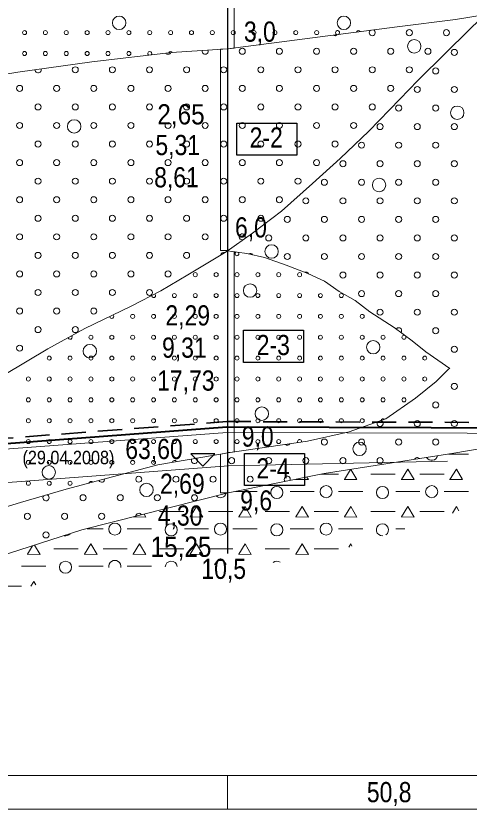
# Model space of a CAD drawing. Extents: x 640121 to 640955, y 6441885 to 6442246.
# Drawn here: x 640296.5 to 640363.9, y 6442063 to 6442180.9 of the extents above; entities that cross this region are included whole.
import ezdxf
from ezdxf.enums import TextEntityAlignment as Align

# ---------------------------------------------------------------- set-up
doc = ezdxf.new("R2010")
doc.units = 0
doc.header["$LTSCALE"] = 1.2
doc.linetypes.add('MEDIUM_DASHED', pattern=[4.5, 3, -1.5])
for name, color, linetype, lineweight in [('30', 7, 'Continuous', 13), ('31', 7, 'Continuous', 13), ('32', 7, 'Continuous', 13), ('33', 7, 'Continuous', 13), ('34', 7, 'Continuous', 25), ('35', 7, 'Continuous', 35), ('42', 7, 'Continuous', 13), ('43', 7, 'Continuous', 13), ('46', 7, 'Continuous', 13), ('47', 7, 'Continuous', 13)]:
    doc.layers.add(name, color=color, linetype=linetype, lineweight=lineweight)

msp = doc.modelspace()

# ---------------------------------------------------------------- linework, layer by layer
at = {"layer": '30'}
for p, q in [((640132.09, 6442068), (640510.5, 6442068)), ((640327.97, 6442068), (640327.97, 6442063)), ((640132.09, 6442063), (640510.5, 6442063))]:
    msp.add_line(p, q, dxfattribs=at)
at = {"layer": '31'}
for points in [[(640247.7, 6442147.03), (640257.72, 6442155.14), (640263.61, 6442159.68), (640268.14, 6442162.86), (640273.1, 6442165.63), (640278.29, 6442168.02), (640283.66, 6442169.95), (640287.74, 6442171.02), (640296.83, 6442172.52), (640307.85, 6442174.05), (640319.67, 6442175.43), (640328.02, 6442175.98), (640353.21, 6442179.27), (640361.87, 6442180.35), (640370.38, 6442181.71)], [(640227.02, 6442092.74), (640246.99, 6442098.72), (640259.67, 6442104.25), (640268.82, 6442109.45), (640277.74, 6442115.86), (640286.04, 6442121.74), (640294.93, 6442127.57), (640301.29, 6442131.41), (640306.79, 6442134.4), (640313.67, 6442137.73), (640318.09, 6442140.03), (640322.12, 6442142.41), (640327.78, 6442145.84), (640331.69, 6442148.58), (640336.02, 6442151.86), (640340.61, 6442155.98), (640344.72, 6442159.66), (640348.97, 6442163.76), (640353.58, 6442168.51), (640356.29, 6442171.26), (640360.44, 6442175.41), (640363.8, 6442178.7), (640365.59, 6442180.42)], [(640156.71, 6442084.57), (640169.39, 6442084.94), (640174.39, 6442085), (640185.27, 6442085.01), (640198.57, 6442085.15), (640211.29, 6442085.53), (640222.23, 6442086.04), (640236.05, 6442086.58), (640247.59, 6442087.26), (640261.87, 6442089), (640272.13, 6442093.03), (640281.27, 6442096.49), (640290.79, 6442099.48), (640306.37, 6442104.48), (640328.11, 6442110.01), (640342.33, 6442112.86), (640361.6, 6442115.89), (640378.77, 6442118.83), (640434.25, 6442118.61), (640476.5, 6442139.76), (640496.42, 6442148.93), (640502.36, 6442149.59), (640510.5, 6442150.13)], [(640327.97, 6442145.97), (640330.88, 6442145.58), (640333.5, 6442144.98), (640336.7, 6442143.84), (640339.93, 6442142.58), (640342.38, 6442141.44), (640344.57, 6442139.91), (640346.94, 6442138.57), (640349.14, 6442136.88), (640352.76, 6442134.56), (640355.44, 6442132.59), (640357.46, 6442130.94), (640361.02, 6442128.5), (640360.83, 6442128.38), (640358.98, 6442126.53), (640355.91, 6442124.09), (640351.5, 6442121.02), (640346.07, 6442119.05), (640339.86, 6442117.66), (640328.38, 6442116.02), (640317.66, 6442114.17), (640310.89, 6442112.36), (640304.04, 6442110.55), (640297.25, 6442108.56), (640288.87, 6442106.02)]]:
    msp.add_lwpolyline(points, dxfattribs=at)
at = {"layer": '32', "lineweight": 25}
msp.add_line((640327.97, 6442205.97), (640327.97, 6442101), dxfattribs=at)
at = {"layer": '33'}
for points in [[(640328.97, 6442176.1), (640328.97, 6442202), (640328, 6442202), (640327.97, 6442202), (640327.97, 6442176), (640328.02, 6442176), (640328.14, 6442176)], [(640326.97, 6442175.91), (640326.97, 6442146), (640327.97, 6442146), (640327.97, 6442146), (640327.97, 6442175.98)], [(640328.97, 6442116.1), (640328.97, 6442145.83), (640327.97, 6442145.97), (640327.97, 6442116), (640328.25, 6442116), (640328.38, 6442116.02)], [(640326.97, 6442115.77), (640326.97, 6442110), (640327.97, 6442110), (640327.97, 6442115.95)]]:
    msp.add_lwpolyline(points, close=True, dxfattribs=at)
at = {"layer": '33', "lineweight": 25}
for points in [[(640329.39, 6442164.94), (640338.31, 6442164.94), (640338.31, 6442160.16), (640329.39, 6442160.16)], [(640330.35, 6442134.17), (640339.27, 6442134.17), (640339.27, 6442129.39), (640330.35, 6442129.39)], [(640330.51, 6442115.87), (640339.43, 6442115.87), (640339.43, 6442111.09), (640330.51, 6442111.09)]]:
    msp.add_lwpolyline(points, close=True, dxfattribs=at)
at = {"layer": '34'}
msp.add_lwpolyline([(640322.56, 6442115.79), (640324.35, 6442113.98), (640326.12, 6442115.79)], close=True, dxfattribs=at)
at = {"layer": '34', "lineweight": 13}
msp.add_lwpolyline([(640159.63, 6442104.37), (640185.19, 6442105.55), (640261.87, 6442109), (640328.12, 6442114), (640360.69, 6442114.7)], dxfattribs=at)
at = {"layer": '35', "linetype": 'MEDIUM_DASHED'}
msp.add_lwpolyline([(640260.27, 6442115.49), (640327.87, 6442120.59), (640433.96, 6442120.25)], dxfattribs=at)
at = {"layer": '35', "lineweight": 40}
msp.add_lwpolyline([(640261.07, 6442114.75), (640327.9, 6442119.79), (640434.15, 6442119.45)], dxfattribs=at)
at = {"layer": '35', "lineweight": 13}
msp.add_lwpolyline([(640261.87, 6442114.01), (640327.93, 6442118.99), (640434.96, 6442118.65)], dxfattribs=at)
at = {"layer": '42'}
for centre in [(640355.008, 6442178.38), (640360.523, 6442178.38), (640330.188, 6442175.622), (640335.704, 6442175.622), (640341.219, 6442175.622), (640346.735, 6442175.622), (640352.25, 6442175.622), (640357.765, 6442175.622), (640361.693, 6442175.455), (640305.369, 6442172.865), (640310.884, 6442172.865), (640316.4, 6442172.865), (640321.915, 6442172.865), (640327.431, 6442172.865), (640332.946, 6442172.865), (640338.461, 6442172.865), (640343.977, 6442172.865), (640349.492, 6442172.865), (640355.008, 6442172.865), (640358.935, 6442172.697), (640297.096, 6442170.107), (640302.611, 6442170.107), (640308.127, 6442170.107), (640313.642, 6442170.107), (640319.157, 6442170.107), (640324.673, 6442170.107), (640330.188, 6442170.107), (640335.704, 6442170.107), (640341.219, 6442170.107), (640346.735, 6442170.107), (640352.25, 6442170.107), (640356.177, 6442169.94), (640361.693, 6442169.94), (640299.853, 6442167.349), (640305.369, 6442167.349), (640310.884, 6442167.349), (640316.4, 6442167.349), (640321.915, 6442167.349), (640327.431, 6442167.349), (640332.946, 6442167.349), (640338.461, 6442167.349), (640343.977, 6442167.349), (640349.492, 6442167.349), (640353.419, 6442167.182), (640358.935, 6442167.182), (640297.096, 6442164.592), (640302.611, 6442164.592), (640308.127, 6442164.592), (640313.642, 6442164.592), (640319.157, 6442164.592), (640324.673, 6442164.592), (640330.188, 6442164.592), (640335.704, 6442164.592), (640341.219, 6442164.592), (640346.735, 6442164.592), (640350.662, 6442164.424), (640356.177, 6442164.424), (640361.693, 6442164.424), (640299.853, 6442161.834), (640305.369, 6442161.834), (640310.884, 6442161.834), (640316.4, 6442161.834), (640321.915, 6442161.834), (640327.431, 6442161.834), (640332.946, 6442161.834), (640338.461, 6442161.834), (640343.977, 6442161.834), (640347.904, 6442161.667), (640353.419, 6442161.667), (640358.935, 6442161.667), (640297.096, 6442159.076), (640302.611, 6442159.076), (640308.127, 6442159.076), (640313.642, 6442159.076), (640319.157, 6442159.076), (640324.673, 6442159.076), (640330.188, 6442159.076), (640335.704, 6442159.076), (640341.219, 6442159.076), (640345.146, 6442158.909), (640350.662, 6442158.909), (640356.177, 6442158.909), (640361.693, 6442158.909), (640299.853, 6442156.318), (640305.369, 6442156.318), (640310.884, 6442156.318), (640316.4, 6442156.318), (640321.915, 6442156.318), (640327.431, 6442156.318), (640332.946, 6442156.318), (640338.461, 6442156.318), (640342.389, 6442156.151), (640347.904, 6442156.151), (640353.419, 6442156.151), (640358.935, 6442156.151), (640297.096, 6442153.561), (640302.611, 6442153.561), (640308.127, 6442153.561), (640313.642, 6442153.561), (640319.157, 6442153.561), (640324.673, 6442153.561), (640330.188, 6442153.561), (640335.704, 6442153.561), (640339.631, 6442153.393), (640345.146, 6442153.393), (640350.662, 6442153.393), (640356.177, 6442153.393), (640361.693, 6442153.393), (640299.853, 6442150.803), (640305.369, 6442150.803), (640310.884, 6442150.803), (640316.4, 6442150.803), (640321.915, 6442150.803), (640327.431, 6442150.803), (640332.946, 6442150.803), (640336.873, 6442150.636), (640342.389, 6442150.636), (640347.904, 6442150.636), (640353.419, 6442150.636), (640358.935, 6442150.636), (640297.096, 6442148.045), (640302.611, 6442148.045), (640308.127, 6442148.045), (640313.642, 6442148.045), (640319.157, 6442148.045), (640324.673, 6442148.045), (640334.115, 6442147.878), (640339.631, 6442147.878), (640345.146, 6442147.878), (640350.662, 6442147.878), (640356.177, 6442147.878), (640361.693, 6442147.878), (640299.853, 6442145.288), (640305.369, 6442145.288), (640310.884, 6442145.288), (640316.4, 6442145.288), (640321.915, 6442145.288), (640336.873, 6442145.12), (640342.389, 6442145.12), (640347.904, 6442145.12), (640353.419, 6442145.12), (640358.935, 6442145.12), (640297.096, 6442142.53), (640302.611, 6442142.53), (640308.127, 6442142.53), (640313.642, 6442142.53), (640319.157, 6442142.53), (640345.146, 6442142.363), (640350.662, 6442142.363), (640356.177, 6442142.363), (640361.693, 6442142.363), (640299.853, 6442139.772), (640305.369, 6442139.772), (640310.884, 6442139.772), (640316.4, 6442139.772), (640347.904, 6442139.605), (640353.419, 6442139.605), (640358.935, 6442139.605), (640297.096, 6442137.014), (640302.611, 6442137.014), (640308.127, 6442137.014), (640350.662, 6442136.847), (640356.177, 6442136.847), (640361.693, 6442136.847), (640299.853, 6442134.257), (640305.369, 6442134.257), (640358.935, 6442134.089), (640297.096, 6442131.499), (640361.693, 6442131.332), (640361.693, 6442125.816), (640358.935, 6442123.059), (640356.177, 6442120.301), (640361.693, 6442120.301), (640342.389, 6442117.543), (640347.904, 6442117.543), (640353.419, 6442117.543), (640358.935, 6442117.543), (640328.6, 6442114.785), (640334.115, 6442114.785), (640339.631, 6442114.785), (640345.146, 6442114.785), (640350.662, 6442114.785), (640314.811, 6442112.028), (640320.327, 6442112.028), (640325.842, 6442112.028), (640331.358, 6442112.028), (640306.538, 6442109.27), (640312.054, 6442109.27), (640317.569, 6442109.27), (640323.085, 6442109.27), (640298.265, 6442106.512), (640303.781, 6442106.512), (640309.296, 6442106.512), (640301.023, 6442103.754)]:
    msp.add_circle(centre, 0.45, dxfattribs=at)
for centre, start, end in [((640349.492, 6442178.38), 123.9399, 70.95075), ((640343.977, 6442178.38), 231.33114, 323.55952), ((640324.673, 6442175.622), 165.75854, 21.72374), ((640319.157, 6442175.622), 219.8752, 333.49226), ((640299.853, 6442172.865), 178.41278, 17.39021), ((640330.188, 6442148.045), 323.19074, 286.75079), ((640327.431, 6442145.288), 71.50649, 170.86346), ((640331.358, 6442145.12), 35.82114, 118.59132), ((640339.631, 6442142.363), 21.69272, 114.17229), ((640353.419, 6442134.089), 321.78206, 145.56429), ((640350.662, 6442120.301), 139.98675, 79.84606), ((640336.873, 6442117.543), 231.54647, 324.71373), ((640323.085, 6442114.785), 145.20426, 54.33119), ((640356.177, 6442114.785), 43.10877, 154.79014), ((640336.873, 6442112.028), 336.41166, 226.29714), ((640309.296, 6442112.028), 205.62604, 3.99072), ((640301.023, 6442109.27), 138.67391, 74.00744), ((640314.811, 6442106.512), 28.16074, 180.36962)]:
    msp.add_arc(centre, 0.45, start, end, dxfattribs=at)
at = {"layer": '43'}
for centre in [(640297.838, 6442178.39), (640300.938, 6442178.39), (640304.038, 6442178.39), (640307.138, 6442178.39), (640310.238, 6442178.39), (640313.338, 6442178.39), (640316.438, 6442178.39), (640319.538, 6442178.39), (640322.638, 6442178.39), (640325.738, 6442178.39), (640328.838, 6442178.39), (640331.938, 6442178.39), (640335.038, 6442178.39), (640338.138, 6442178.39), (640341.238, 6442178.39), (640297.838, 6442175.29), (640300.938, 6442175.29), (640304.038, 6442175.29), (640307.138, 6442175.29), (640310.238, 6442175.29), (640313.338, 6442175.29), (640323.203, 6442142.42), (640326.303, 6442142.42), (640329.403, 6442142.42), (640332.503, 6442142.42), (640335.603, 6442142.42), (640338.703, 6442142.42), (640320.103, 6442139.32), (640323.203, 6442139.32), (640326.303, 6442139.32), (640329.403, 6442139.32), (640332.503, 6442139.32), (640335.603, 6442139.32), (640338.703, 6442139.32), (640341.803, 6442139.32), (640344.903, 6442139.32), (640313.903, 6442136.22), (640317.003, 6442136.22), (640320.103, 6442136.22), (640323.203, 6442136.22), (640326.303, 6442136.22), (640329.403, 6442136.22), (640332.503, 6442136.22), (640335.603, 6442136.22), (640338.703, 6442136.22), (640341.803, 6442136.22), (640344.903, 6442136.22), (640348.003, 6442136.22), (640307.703, 6442133.12), (640310.803, 6442133.12), (640313.903, 6442133.12), (640317.003, 6442133.12), (640320.103, 6442133.12), (640323.203, 6442133.12), (640326.303, 6442133.12), (640329.403, 6442133.12), (640332.503, 6442133.12), (640335.603, 6442133.12), (640338.703, 6442133.12), (640341.803, 6442133.12), (640344.903, 6442133.12), (640348.003, 6442133.12), (640351.103, 6442133.12), (640354.203, 6442133.12), (640301.503, 6442130.02), (640304.603, 6442130.02), (640307.703, 6442130.02), (640310.803, 6442130.02), (640313.903, 6442130.02), (640317.003, 6442130.02), (640320.103, 6442130.02), (640323.203, 6442130.02), (640326.303, 6442130.02), (640329.403, 6442130.02), (640332.503, 6442130.02), (640335.603, 6442130.02), (640338.703, 6442130.02), (640341.803, 6442130.02), (640344.903, 6442130.02), (640348.003, 6442130.02), (640351.103, 6442130.02), (640354.203, 6442130.02), (640357.303, 6442130.02), (640298.403, 6442126.92), (640301.503, 6442126.92), (640304.603, 6442126.92), (640307.703, 6442126.92), (640310.803, 6442126.92), (640313.903, 6442126.92), (640317.003, 6442126.92), (640320.103, 6442126.92), (640323.203, 6442126.92), (640326.303, 6442126.92), (640329.403, 6442126.92), (640332.503, 6442126.92), (640335.603, 6442126.92), (640338.703, 6442126.92), (640341.803, 6442126.92), (640344.903, 6442126.92), (640348.003, 6442126.92), (640351.103, 6442126.92), (640354.203, 6442126.92), (640357.303, 6442126.92), (640298.403, 6442123.82), (640301.503, 6442123.82), (640304.603, 6442123.82), (640307.703, 6442123.82), (640310.803, 6442123.82), (640313.903, 6442123.82), (640317.003, 6442123.82), (640320.103, 6442123.82), (640323.203, 6442123.82), (640326.303, 6442123.82), (640329.403, 6442123.82), (640332.503, 6442123.82), (640335.603, 6442123.82), (640338.703, 6442123.82), (640341.803, 6442123.82), (640344.914, 6442123.822), (640348.003, 6442123.82), (640351.103, 6442123.82), (640354.203, 6442123.82), (640298.403, 6442120.72), (640301.503, 6442120.72), (640304.603, 6442120.72), (640307.703, 6442120.72), (640310.803, 6442120.72), (640313.903, 6442120.72), (640317.003, 6442120.72), (640320.103, 6442120.72), (640323.203, 6442120.72), (640326.303, 6442120.72), (640329.403, 6442120.72), (640332.503, 6442120.72), (640335.603, 6442120.72), (640338.703, 6442120.72), (640341.803, 6442120.72), (640344.903, 6442120.72), (640348.003, 6442120.72), (640298.403, 6442117.62), (640301.503, 6442117.62), (640304.603, 6442117.62), (640307.703, 6442117.62), (640310.803, 6442117.62), (640313.903, 6442117.62), (640317.003, 6442117.62), (640320.103, 6442117.62), (640323.203, 6442117.62), (640326.303, 6442117.62), (640329.403, 6442117.62), (640332.503, 6442117.62), (640335.603, 6442117.62), (640298.403, 6442114.52), (640301.503, 6442114.52), (640304.603, 6442114.52), (640307.703, 6442114.52), (640310.803, 6442114.52), (640313.903, 6442114.52), (640317.003, 6442114.52), (640298.403, 6442111.42), (640301.503, 6442111.42), (640304.603, 6442111.42)]:
    msp.add_circle(centre, 0.3, dxfattribs=at)
for centre, start, end in [((640344.338, 6442178.39), 300.84672, 254.04393), ((640347.438, 6442178.39), 32.35878, 162.53188), ((640316.438, 6442175.29), 315.70018, 237.66727), ((640319.538, 6442175.29), 30.52408, 161.48764), ((640329.403, 6442145.52), 114.89734, 49.71055), ((640317.003, 6442139.32), 182.74217, 52.14607), ((640310.803, 6442136.22), 184.52562, 47.17663), ((640304.603, 6442133.12), 193.32451, 43.66677), ((640351.103, 6442120.72), 49.02958, 170.80323), ((640338.703, 6442117.62), 343.23941, 213.02079), ((640320.103, 6442114.52), 23.61955, 175.9159), ((640307.703, 6442111.42), 33.51584, 176.10091)]:
    msp.add_arc(centre, 0.3, start, end, dxfattribs=at)
at = {"layer": '46'}
for p, q in [((640363.78, 6442115.77), (640360.83, 6442115.77)), ((640344.49, 6442112.78), (640341.92, 6442112.78)), ((640352.89, 6442112.78), (640349.29, 6442112.78)), ((640360.18, 6442112.78), (640356.58, 6442112.78)), ((640332.39, 6442110.22), (640329.17, 6442110.22)), ((640340.89, 6442110.22), (640337.29, 6442110.22)), ((640348.09, 6442110.22), (640344.49, 6442110.22)), ((640356.58, 6442110.22), (640352.98, 6442110.22)), ((640363.78, 6442110.22), (640360.18, 6442110.22)), ((640313.96, 6442106.4), (640313.96, 6442106.41)), ((640321.5, 6442107.23), (640317.9, 6442107.23)), ((640328.79, 6442107.22), (640325.19, 6442107.22)), ((640337.19, 6442107.23), (640333.59, 6442107.23)), ((640344.49, 6442107.22), (640340.89, 6442107.22)), ((640352.89, 6442107.23), (640349.29, 6442107.23)), ((640360.18, 6442107.22), (640356.58, 6442107.22)), ((640309.5, 6442104.67), (640307.13, 6442104.67)), ((640316.7, 6442104.66), (640313.1, 6442104.66)), ((640325.19, 6442104.67), (640321.59, 6442104.67)), ((640332.39, 6442104.66), (640328.79, 6442104.66)), ((640340.89, 6442104.67), (640337.29, 6442104.67)), ((640348.09, 6442104.66), (640344.49, 6442104.66)), ((640354.33, 6442104.67), (640352.98, 6442104.67)), ((640305.8, 6442101.67), (640302.2, 6442101.67)), ((640313.1, 6442101.67), (640309.5, 6442101.67)), ((640321.5, 6442101.67), (640317.9, 6442101.67)), ((640328.79, 6442101.67), (640325.19, 6442101.67)), ((640337.19, 6442101.67), (640333.59, 6442101.67)), ((640344.49, 6442101.67), (640340.89, 6442101.67)), ((640301, 6442099.11), (640297.4, 6442099.11)), ((640309.5, 6442099.12), (640305.9, 6442099.12)), ((640316.7, 6442099.11), (640313.1, 6442099.11)), ((640297.4, 6442096.12), (640293.8, 6442096.12))]:
    msp.add_line(p, q, dxfattribs=at)
for points in [[(640345.35, 6442111.95), (640345.35, 6442111.97), (640346.28, 6442113.48)], [(640346.31, 6442113.49), (640347.23, 6442111.96), (640345.43, 6442111.97)], [(640353.82, 6442111.95), (640353.82, 6442111.97), (640354.77, 6442113.51), (640355.7, 6442111.96), (640353.9, 6442111.97)], [(640361.04, 6442111.95), (640361.04, 6442111.97), (640361.99, 6442113.51), (640362.92, 6442111.96), (640361.12, 6442111.97)], [(640339.77, 6442112.35), (640340.01, 6442111.96), (640338.21, 6442111.97)], [(640338.12, 6442111.95), (640338.13, 6442111.97), (640338.16, 6442112.02)], [(640322.43, 6442106.4), (640322.43, 6442106.42), (640323.38, 6442107.95), (640324.31, 6442106.41), (640322.51, 6442106.42)], [(640329.65, 6442106.4), (640329.65, 6442106.42), (640330.6, 6442107.95), (640331.53, 6442106.41), (640329.73, 6442106.42)], [(640338.12, 6442106.4), (640338.13, 6442106.42), (640339.07, 6442107.95), (640340.01, 6442106.41), (640338.21, 6442106.42)], [(640345.35, 6442106.4), (640345.35, 6442106.42), (640346.3, 6442107.95), (640347.23, 6442106.41), (640345.43, 6442106.42)], [(640353.82, 6442106.4), (640353.82, 6442106.42), (640354.77, 6442107.95), (640355.7, 6442106.41), (640353.9, 6442106.42)], [(640361.4, 6442106.99), (640361.99, 6442107.95), (640362.37, 6442107.32)], [(640315.59, 6442106.82), (640315.84, 6442106.41), (640314.04, 6442106.42)], [(640298.26, 6442100.84), (640298.26, 6442100.87), (640299.04, 6442102.13)], [(640299.32, 6442102.21), (640300.14, 6442100.86), (640298.34, 6442100.87)], [(640306.73, 6442100.84), (640306.74, 6442100.87), (640307.68, 6442102.4), (640308.61, 6442100.86), (640306.81, 6442100.87)], [(640313.96, 6442100.84), (640313.96, 6442100.87), (640314.91, 6442102.4), (640315.84, 6442100.86), (640314.04, 6442100.87)], [(640322.43, 6442100.84), (640322.43, 6442100.87), (640323.38, 6442102.4), (640324.31, 6442100.86), (640322.51, 6442100.87)], [(640329.65, 6442100.84), (640329.65, 6442100.87), (640330.6, 6442102.4), (640331.53, 6442100.86), (640329.73, 6442100.87)], [(640338.12, 6442100.84), (640338.13, 6442100.87), (640339.07, 6442102.4), (640340.01, 6442100.86), (640338.21, 6442100.87)], [(640346.01, 6442101.94), (640346.3, 6442102.4), (640346.48, 6442102.09)], [(640298.75, 6442096.11), (640299.21, 6442096.84), (640299.51, 6442096.34)]]:
    msp.add_lwpolyline(points, dxfattribs=at)
for centre in [(640335.321, 6442110.051), (640342.634, 6442110.173), (640351.016, 6442110.051), (640358.329, 6442110.173), (640311.244, 6442104.618), (640319.626, 6442104.496), (640326.939, 6442104.618), (640335.321, 6442104.496), (640342.634, 6442104.618), (640303.931, 6442098.942)]:
    msp.add_circle(centre, 0.9, dxfattribs=at)
for centre, start, end in [((640358.329, 6442115.727), 211.34495, 346.55396), ((640326.939, 6442110.173), 224.36087, 344.1695), ((640351.016, 6442104.496), 303.20114, 273.1549), ((640303.931, 6442104.496), 255.84917, 319.74281), ((640311.244, 6442099.064), 348.83744, 191.16256), ((640319.626, 6442098.942), 8.66472, 175.9165), ((640326.939, 6442099.064), 19.75778, 164.82344), ((640335.321, 6442098.942), 56.19421, 128.38701)]:
    msp.add_arc(centre, 0.9, start, end, dxfattribs=at)
at = {"layer": '47'}
for centre in [(640311.89, 6442179.843), (640345.284, 6442179.843), (640355.738, 6442176.358), (640362.127, 6442166.485), (640305.211, 6442164.453), (640350.511, 6442155.741), (640334.54, 6442145.868), (640331.346, 6442140.06), (640349.64, 6442131.639), (640307.534, 6442131.058), (640333.088, 6442121.766), (640347.607, 6442116.539), (640301.436, 6442113.054), (640315.955, 6442110.441)]:
    msp.add_circle(centre, 1, dxfattribs=at)

# ---------------------------------------------------------------- texts
at = {"layer": '30', "width": 0.85}
msp.add_text('50,8', height=3, dxfattribs=at).set_placement((640352.01, 6442064.03), align=Align.CENTER)
at = {"layer": '32'}
for s, width, p in [('3,0', 0.85, (640332.8, 6442177.04)), ('2,65', 0.9, (640321.08, 6442164.75)), ('8,61', 0.85, (640320.41, 6442155.4)), ('6,0', 0.85, (640331.475, 6442147.95)), ('2,29', 0.85, (640322.08, 6442134.87)), ('17,73', 0.85, (640321.8, 6442125.19)), ('9,0', 0.85, (640332.48, 6442116.87)), ('2,69', 0.85, (640321.28, 6442109.86)), ('9,6', 0.85, (640332.245, 6442107.37)), ('15,25', 0.9, (640321.085, 6442100.49)), ('10,5', 0.85, (640327.43, 6442097.21))]:
    msp.add_text(s, height=3, dxfattribs=dict(at, width=width)).set_placement(p, align=Align.CENTER)
at = {"layer": '33', "width": 0.85}
for s, p in [('2-2', (640333.74, 6442161.3)), ('5,31', (640320.595, 6442160.19)), ('2-3', (640334.8, 6442130.47)), ('9,31', (640321.585, 6442130.08)), ('2-4', (640334.755, 6442112.14)), ('4,30', (640320.95, 6442105.13))]:
    msp.add_text(s, height=3, dxfattribs=at).set_placement(p, align=Align.CENTER)
at = {"layer": '34'}
for s, height, width, p in [('63,60', 3, 0.85, (640317.07, 6442115.02)), ('(29.04.2008)', 2, 0.9, (640304.36, 6442114.25))]:
    msp.add_text(s, height=height, dxfattribs=dict(at, width=width)).set_placement(p, align=Align.CENTER)

doc.saveas('drawing.dxf')
